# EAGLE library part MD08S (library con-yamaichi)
YAMAICHI CONNECTOR
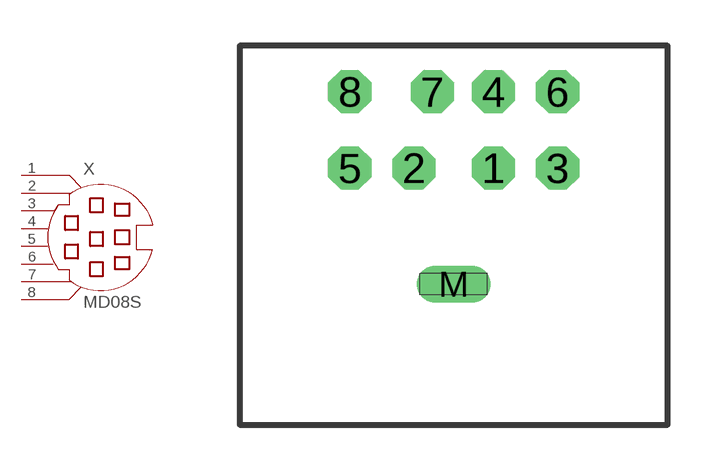
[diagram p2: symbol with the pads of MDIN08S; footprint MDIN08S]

Designator prefix X

## MD08S (OC_FARNELL: unknown; OC_NEWARK: unknown)  [MDIN08S]
1  1  pas
2  2  pas
3  3  pas
4  4  pas
5  5  pas
6  6  pas
7  7  pas
8  8  pas

## Footprint MDIN08S (pad centres in mm)
Mini Din YAMAICHI CONNECTOR
drill 0.9 octagon: 1 1.3,8.5; 2 -1.3,8.5; 3 3.4,8.5; 4 1.3,11; 5 -3.4,8.5; 6 3.4,11; 7 -0.7,11; 8 -3.4,11
drill 0.7 long: M 0,4.7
